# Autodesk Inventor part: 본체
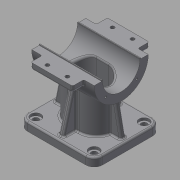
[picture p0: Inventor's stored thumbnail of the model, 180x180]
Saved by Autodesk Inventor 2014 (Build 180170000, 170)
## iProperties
Created: 2015-12
Part Number: 본체
Material: 일반
Document SubType Name: Modeling
Designer: mduedu
Density: 1 g/cm^3
Appearance: 기본값
Mass: 175.423 g
Surface Area: 479.255 cm^2
Volume: 175.423 cm^3
Author: mduedu
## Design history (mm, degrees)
sketch "스케치1"
  geometry: L1 (45, 40)-(-45, 40); L2 (-45, 40)-(-45, -40); L3 (-45, -40)-(45, -40); L4 (45, -40)-(45, 40); L5 (45, 40)-(-45, -40); L6 (-45, 40)-(45, -40); 1 further point
  constraints: 12 end point, 2 midpoint, 2 parallel, 1 horizontal, 1 perpendicular
  dimensions: "d0" = 90 distance of L2.end L3.end; "d2" = 80 distance of L1.end L2.end
extrude "돌출1" new body sketch "스케치1" distance "d3" = 10; taper "d4" = 0 deg
sketch "스케치2"
  geometry: L1 (0, 40)-(0, -40) reference; C1 r 32.5 at (80, 0); 1 further point
  constraints: 1 centre point
  dimensions: "d5" = 65 diameter of C1; "d6" = 80 distance from line of C1.centre L1
extrude "돌출2" join sketch "스케치2" stored distance "d7" = 75; taper "d8" = 0 deg
sketch "스케치3"
  geometry: L1 (-27.5, -20)-(27.5, -20); L2 (27.5, -20)-(27.5, 20); L3 (27.5, 20)-(-27.5, 20); L4 (-27.5, 20)-(-27.5, -20); L5 (-27.5, -20)-(27.5, 20); L6 (27.5, -20)-(-27.5, 20); 1 further point
  constraints: 12 end point, 2 midpoint, 2 parallel, 1 horizontal, 1 perpendicular
  dimensions: "d9" = 55 distance of L2.end L3.end; "d11" = 40 distance of L1.end L2.end
extrude "돌출3" new body sketch "스케치3" stored distance "d12" = 75; taper "d13" = 0 deg
fillet "모깎기1"
fillet "모깎기2"
feature "결합1"
  node "솔리드2"
fillet "모깎기3" dims "d14" = 10
sketch "스케치4"
  geometry: L1 (-37.5, 47.5)-(37.5, 47.5) reference; L2 (35, 10)-(45, 10) reference; L3 (32.5, 47.5)-(40, 10); L4 (37.5, 47.5)-(37.5, 112.5) reference; L5 (45, 10)-(45, 0) reference; 1 further point
  constraints: 2 end point, 1 midpoint, 1 point on line
  dimensions: "d15" = 5 distance from line of L3.start L4; "d16" = 5 distance from line of L3.end L5
sketch "스케치5"
  geometry: L1 (10, 40)-(10, 30) reference; L2 (10, 35)-(56.569, 22.522); L3 (0, 40)-(10, 40) reference; 2 further points
  constraints: 2 end point, 1 midpoint, 2 other
  dimensions: "d17" = 5 distance from line of L2.start L3; "d18" = 15 deg angle of L2 L3
feature "리브1" dims "d19" = 1, "d20" = 6, "d21" = 0, "d22" = 0, "d23" = 1, "d24" = 1
feature "리브2" dims "d25" = 1, "d26" = 6, "d27" = 0, "d28" = 0, "d29" = 1, "d30" = 1
fillet "모깎기4" dims "d31" = 2
fillet "모깎기5" dims "d32" = 2
fillet "모깎기6" dims "d33" = 2
sketch "스케치6"
  geometry: A1 r 10 centre (-35, 30) between (-35, 40) and (-45, 30) reference; A2 r 10 centre (35, 30) between (45, 30) and (35, 40) reference; A3 r 10 centre (35, -30) between (35, -40) and (45, -30) reference; A4 r 10 centre (-35, -30) between (-45, -30) and (-35, -40) reference; 5 further points
  constraints: 4 coincident
hole "구멍1" sketch "스케치6" at (-35, 30), (35, 30), (35, -30), (-35, -30) diameter "d34" = 7; stored, may be unused: countersink angle "d38" = 90 deg, drill point angle "d40" = 118 deg; dims "d35" = 6, "d36" = 12, "d37" = 3, "d39" = 8
fillet "모깎기7" dims "d41" = 2
hole "구멍2" diameter "d44" = 45; stored, may be unused: countersink angle "d48" = 90 deg, drill point angle "d50" = 118 deg; dims "d42" = 10, "d43" = 10, "d45" = 6, "d46" = 4, "d47" = 2, "d49" = 8
sketch "스케치7" dims "d52" = 26.5
  geometry: L1 (0, 0)-(32.5, 0); L2 (0, 0)-(22.981, 22.981); A1 r 32.5 centre (0, 0) between (32.5, 0) and (22.981, 22.981) reference; 3 further points
  constraints: 4 end point, 2 point on circle, 1 coincident, 1 horizontal, 1 point on line, 3 other
  dimensions: "d51" = 45 deg angle of L2 L1
hole "구멍3" sketch "스케치7" at (18.738, 18.738) diameter "d54" = 2.459; stored, may be unused: countersink angle "d58" = 90 deg, drill point angle "d60" = 118 deg; dims "d55" = 8, "d56" = 4, "d57" = 2, "d59" = 10
sketch "스케치8"
  geometry: L1 (72.5, 31.623)-(72.5, 46); L2 (72.5, 46)-(87.5, 46); L3 (87.5, 46)-(87.5, 31.623); A1 r 32.5 centre (80, 0) between (87.5, 31.623) and (72.5, 31.623) reference; 2 further points
  constraints: 6 end point, 2 point on circle, 1 midpoint, 1 parallel, 1 vertical, 1 vertical alignment
  dimensions: "d64" = 15 distance of L1.end L2.end; "d66" = 46 distance from line of L2 A1.centre
extrude "돌출4" join sketch "스케치8" stored distance "d67" = 50; taper "d68" = 0 deg
fillet "모깎기8" dims "d69" = 3
fillet "모깎기9" dims "d70" = 2
sketch "스케치9"
  geometry: L1 (-76, 82.5)-(76, 82.5); L2 (76, 82.5)-(76, 0); L3 (76, 0)-(-76, 0); L4 (-76, 0)-(-76, 82.5); L5 (-46, 4.5)-(-46, -4.5) reference; C1 r 32.5 at (0, 0) reference; 2 further points
  constraints: 8 end point, 2 parallel, 1 coincident, 1 horizontal, 1 midpoint, 1 perpendicular
  dimensions: "d71" = 50 distance edge to line of C1 L1; "d72" = 30 distance between parallel lines of L4 L5
extrude "돌출5" cut sketch "스케치9" stored distance "d73" = 0; taper "d74" = 0 deg
node "작업 평면1"
sketch "스케치10"
  geometry: L1 (-7.5, 15)-(7.5, 15); L2 (-7.5, -15)-(7.5, -15); A1 r 20 centre (-7.5, 0) between (-7.5, 20) and (-26.977, 4.545) reference; A2 r 20 centre (7.5, 0) between (26.977, 4.545) and (7.5, 20) reference; A3 r 15 centre (-7.5, 0) between (-7.5, 15) and (-7.5, -15); A4 r 15 centre (7.5, 0) between (7.5, -15) and (7.5, 15); 1 further point
  constraints: 7 point on circle, 4 end point, 4 tangent, 3 point on line, 2 centre point, 2 coincident, 1 horizontal
  dimensions: "d77" = 5 radial gap between concentric circles of A3 A1
extrude "돌출6" cut sketch "스케치10" stored distance "d78" = 50; taper "d79" = 0 deg
fillet "모깎기10" dims "d80" = 3
sketch "스케치11"
  geometry: 2 further points
  constraints: 1 coincident
hole "구멍4" sketch "스케치11" at (0, 0) diameter "d81" = 12; stored, may be unused: countersink angle "d85" = 90 deg, drill point angle "d87" = 118 deg; dims "d82" = 8, "d83" = 40, "d84" = 10, "d86" = 10
sketch "스케치12"
  geometry: C1 r 10 at (0, 0); 1 further point
  constraints: 1 centre point, 1 coincident
  dimensions: "d88" = 20 diameter of C1
extrude "돌출7" cut sketch "스케치12" distance "d89" = 5; taper "d90" = 0 deg
chamfer "모따기1" distance "d91" = 1; stored, may be unused: second distance "d92" = 2, angle "d93" = 45 deg
fillet "모깎기11" dims "d94" = 0.5
feature "립1" dims "d95" = 1, "d96" = 1, "d97" = 0, "d98" = 3 deg, "d99" = 3 deg, "d100" = 0
sketch "스케치13"
  geometry: 4 further points
hole "구멍5" sketch "스케치13" at (34, 5.936), (10, -72.269), (34, -72.269), (10, 5.936) diameter "d101" = 4.5; stored, may be unused: countersink angle "d105" = 90 deg, drill point angle "d107" = 0 deg; dims "d102" = 6, "d103" = 4, "d104" = 2, "d106" = 8
fillet "모깎기12" dims "d115" = 0.3
node "솔리드1"
mirror "대칭1"
mirror "대칭2"
pattern_circular "원형 패턴1" dims angle "d62" = 360 deg
mirror "대칭3"
mirror "대칭4"
